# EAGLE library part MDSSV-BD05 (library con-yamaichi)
YAMAICHI CONNECTOR
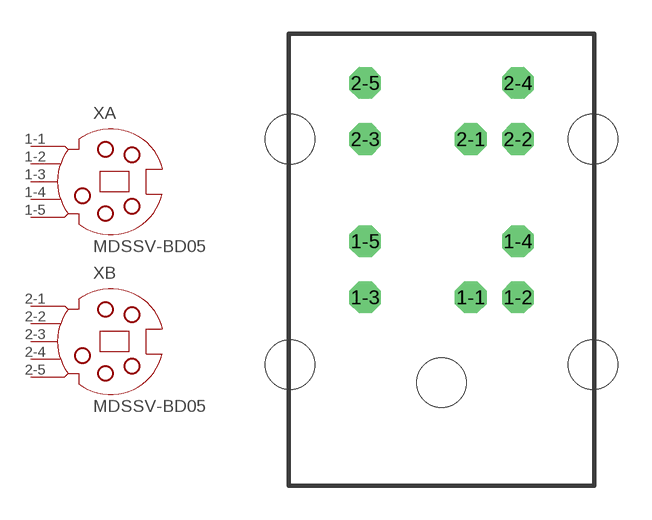
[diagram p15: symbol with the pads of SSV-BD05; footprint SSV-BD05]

Designator prefix X; gates A=SSV-BC05 B=SSV-BC05

## MDSSV-BD05 (OC_FARNELL: unknown; OC_NEWARK: unknown)  [SSV-BD05]
1-1  A:1  pas
1-2  A:2  pas
1-3  A:3  pas
1-4  A:4  pas
1-5  A:5  pas
2-1  B:1  pas
2-2  B:2  pas
2-3  B:3  pas
2-4  B:4  pas
2-5  B:5  pas

## Footprint SSV-BD05 (pad centres in mm)
Mini Din YAMAICHI CONNECTOR
drill 0.9 octagon: 1-1 1.3,8.5; 1-2 3.4,8.5; 1-3 -3.4,8.5; 1-4 3.4,11; 1-5 -3.4,11; 2-1 1.3,15.55; 2-2 3.4,15.55; 2-3 -3.4,15.55; 2-4 3.4,18.05; 2-5 -3.4,18.05
hole 2.2 at -6.75,15.55
hole 2.2 at 0,4.7
hole 2.2 at 6.75,15.55
hole 2.2 at -6.75,5.5
hole 2.2 at 6.75,5.5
